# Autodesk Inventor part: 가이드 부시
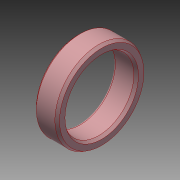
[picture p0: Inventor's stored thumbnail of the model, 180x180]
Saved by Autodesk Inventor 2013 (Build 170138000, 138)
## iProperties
Created: 2023-09
Part Number: 가이드 부시
Material: 스테인리스강
Document SubType Name: Modeling
Designer: mdu-01
Density: 1 g/cm^3
Author: mdu-01
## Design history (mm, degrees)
sketch "스케치1"
  geometry: L1 (0, 0)-(12, 0); L2 (1, 18)-(10.5, 18); L3 (12, 18.866)-(12, 21.634); L4 (10.5, 22.5)-(1, 22.5); L5 (0, 21.5)-(0, 19); L6 (1, 22.5)-(0, 21.5); L7 (10.5, 22.5)-(12, 21.634); L8 (10.5, 18)-(12, 18.866); A1 r 1 centre (1, 19) between (0, 19) and (1, 18); 3 further points
  constraints: 16 end point, 8 point on line, 2 horizontal, 2 parallel, 2 point on circle, 2 tangent, 1 centre point, 1 perpendicular
  dimensions: "d0" = 12 distance of L1.start L1.end; "d1" = 36 diameter of L2 L1; "d2" = 45 diameter of L4 L1; "d3" = 1 radius of A1; "d4" = 1 distance of L4.end point (0, 22.5); "d5" = 1 distance of L5.start point (0, 22.5) (= d4); "d6" = 1.5 distance of L4.start point (12, 22.5); "d7" = 30 deg angle of L4 L7; "d8" = 1.5 distance of L2.end point (12, 18) (= d6); "d9" = 30 deg angle of L2 L8 (= d7)
revolve "회전1" sketch "스케치1" stored, may be unused: angle "d10" = 90 deg
node "솔리드1"
